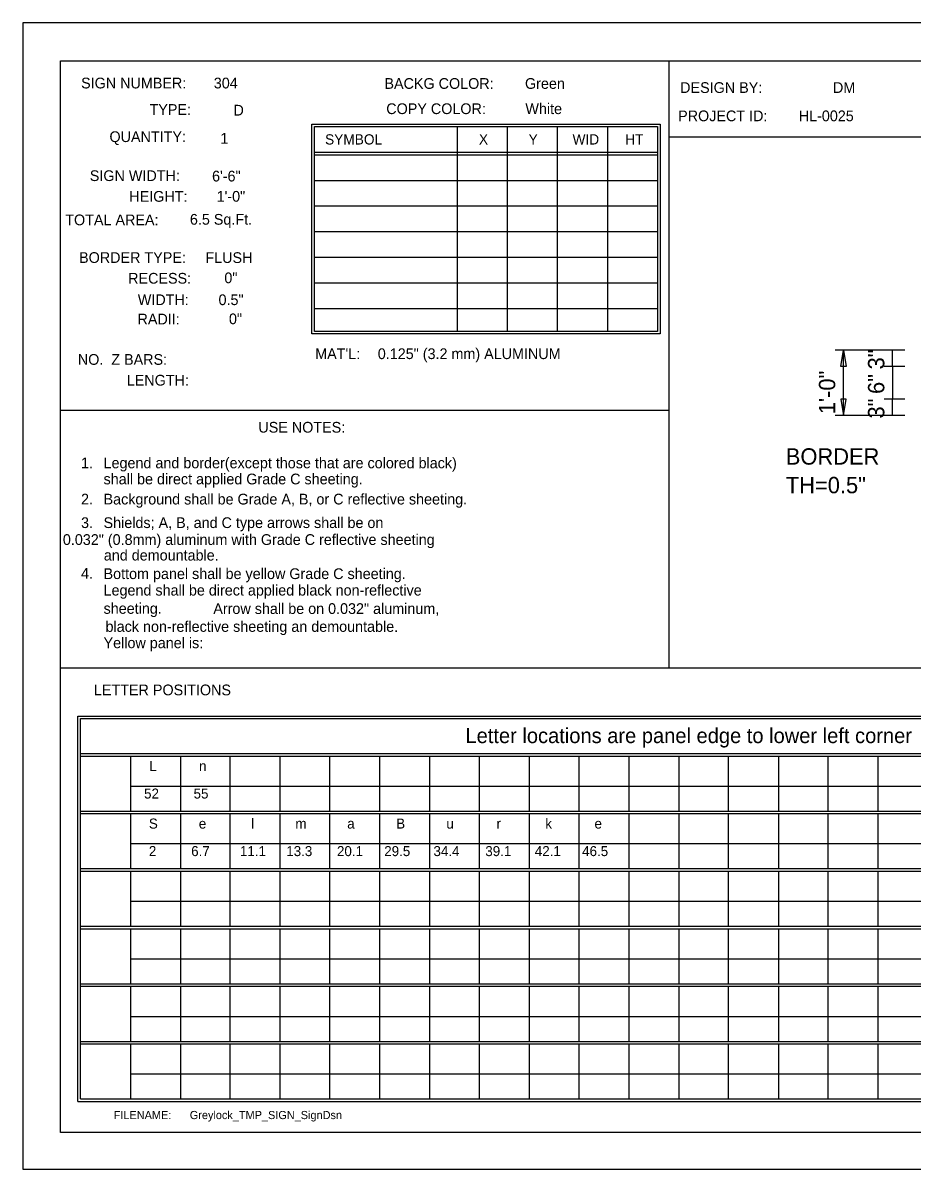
# Model space of a CAD drawing. Extents: x 1708.4 to 1771.6, y 238.3 to 283.4.
# Drawn here: x 1741.57 to 1757.88, y 238.25 to 259.27 of the extents above; entities that cross this region are included whole.
import ezdxf

# ---------------------------------------------------------------- set-up
doc = ezdxf.new("R2010")
doc.units = 0
for name, color, linetype in [('Level 10', 7, 'Continuous'), ('Level 5', 7, 'Continuous'), ('Level 6', 7, 'Continuous'), ('Level 7', 7, 'Continuous'), ('Level 8', 7, 'Continuous'), ('Level 9', 7, 'Continuous')]:
    doc.layers.add(name, color=color, linetype=linetype)

msp = doc.modelspace()

# ---------------------------------------------------------------- linework, layer by layer
at = {"layer": 'Level 5'}
for p, q in [((1756.843, 253.272), (1756.468, 253.272)), ((1756.618, 252.072), (1756.618, 253.272)), ((1757.743, 253.272), (1756.843, 253.272)), ((1757.743, 253.272), (1757.368, 253.272)), ((1757.518, 252.972), (1757.518, 253.272)), ((1757.743, 252.972), (1757.368, 252.972)), ((1757.743, 252.972), (1757.368, 252.972)), ((1757.518, 252.972), (1757.518, 252.372)), ((1757.743, 252.372), (1757.368, 252.372)), ((1757.743, 252.372), (1757.368, 252.372)), ((1757.518, 252.072), (1757.518, 252.372)), ((1756.843, 252.072), (1756.468, 252.072)), ((1757.743, 252.072), (1756.843, 252.072)), ((1757.743, 252.072), (1757.368, 252.072))]:
    msp.add_line(p, q, dxfattribs=at)
for points in [[(1756.618, 253.272), (1756.668, 252.972), (1756.568, 252.972)], [(1756.618, 252.072), (1756.668, 252.371), (1756.568, 252.371)]]:
    msp.add_lwpolyline(points, close=True, dxfattribs=at)
at = {"layer": 'Level 6'}
for p, q in [((1753.415, 258.58), (1753.415, 247.445)), ((1749.531, 257.372), (1749.531, 253.615)), ((1750.45, 257.372), (1750.45, 253.615)), ((1751.37, 257.372), (1751.37, 253.615)), ((1752.29, 257.372), (1752.29, 253.615)), ((1753.415, 257.183), (1770.57, 257.183)), ((1746.917, 256.902), (1753.21, 256.902)), ((1746.917, 256.856), (1753.21, 256.856)), ((1746.917, 256.386), (1753.21, 256.386)), ((1746.917, 255.917), (1753.21, 255.917)), ((1746.917, 255.447), (1753.21, 255.447)), ((1746.917, 254.977), (1753.21, 254.977)), ((1746.917, 254.508), (1753.21, 254.508)), ((1746.917, 254.038), (1753.21, 254.038)), ((1753.415, 252.166), (1742.258, 252.166)), ((1742.258, 247.445), (1753.415, 247.445)), ((1753.415, 247.445), (1770.57, 247.445)), ((1742.622, 245.873), (1764.388, 245.873)), ((1742.622, 245.827), (1764.388, 245.827)), ((1743.539, 245.827), (1743.539, 244.817)), ((1744.457, 245.827), (1744.457, 244.817)), ((1745.366, 245.827), (1745.366, 244.817)), ((1746.283, 245.827), (1746.283, 244.817)), ((1747.192, 245.827), (1747.192, 244.817)), ((1748.11, 245.827), (1748.11, 244.817)), ((1749.027, 245.827), (1749.027, 244.817)), ((1749.936, 245.827), (1749.936, 244.817)), ((1750.854, 245.827), (1750.854, 244.817)), ((1751.762, 245.827), (1751.762, 244.817)), ((1752.68, 245.827), (1752.68, 244.817)), ((1753.598, 245.827), (1753.598, 244.817)), ((1754.506, 245.827), (1754.506, 244.817)), ((1755.424, 245.827), (1755.424, 244.817)), ((1756.332, 245.827), (1756.332, 244.817)), ((1757.25, 245.827), (1757.25, 244.817)), ((1743.539, 245.276), (1764.388, 245.276)), ((1742.622, 244.817), (1764.388, 244.817)), ((1742.622, 244.771), (1764.388, 244.771)), ((1743.539, 244.771), (1743.539, 243.761)), ((1744.457, 244.771), (1744.457, 243.761)), ((1745.366, 244.771), (1745.366, 243.761)), ((1746.283, 244.771), (1746.283, 243.761)), ((1747.192, 244.771), (1747.192, 243.761)), ((1748.11, 244.771), (1748.11, 243.761)), ((1749.027, 244.771), (1749.027, 243.761)), ((1749.936, 244.771), (1749.936, 243.761)), ((1750.854, 244.771), (1750.854, 243.761)), ((1751.762, 244.771), (1751.762, 243.761)), ((1752.68, 244.771), (1752.68, 243.761)), ((1753.598, 244.771), (1753.598, 243.761)), ((1754.506, 244.771), (1754.506, 243.761)), ((1755.424, 244.771), (1755.424, 243.761)), ((1756.332, 244.771), (1756.332, 243.761)), ((1757.25, 244.771), (1757.25, 243.761)), ((1743.539, 244.22), (1764.388, 244.22)), ((1742.622, 243.761), (1764.388, 243.761)), ((1742.622, 243.715), (1764.388, 243.715)), ((1743.539, 243.715), (1743.539, 242.705)), ((1744.457, 243.715), (1744.457, 242.705)), ((1745.366, 243.715), (1745.366, 242.705)), ((1746.283, 243.715), (1746.283, 242.705)), ((1747.192, 243.715), (1747.192, 242.705)), ((1748.11, 243.715), (1748.11, 242.705)), ((1749.027, 243.715), (1749.027, 242.705)), ((1749.936, 243.715), (1749.936, 242.705)), ((1750.854, 243.715), (1750.854, 242.705)), ((1751.762, 243.715), (1751.762, 242.705)), ((1752.68, 243.715), (1752.68, 242.705)), ((1753.598, 243.715), (1753.598, 242.705)), ((1754.506, 243.715), (1754.506, 242.705)), ((1755.424, 243.715), (1755.424, 242.705)), ((1756.332, 243.715), (1756.332, 242.705)), ((1757.25, 243.715), (1757.25, 242.705)), ((1743.539, 243.164), (1764.388, 243.164)), ((1742.622, 242.705), (1764.388, 242.705)), ((1742.622, 242.659), (1764.388, 242.659)), ((1743.539, 242.659), (1743.539, 241.649)), ((1744.457, 242.659), (1744.457, 241.649)), ((1745.366, 242.659), (1745.366, 241.649)), ((1746.283, 242.659), (1746.283, 241.649)), ((1747.192, 242.659), (1747.192, 241.649)), ((1748.11, 242.659), (1748.11, 241.649)), ((1749.027, 242.659), (1749.027, 241.649)), ((1749.936, 242.659), (1749.936, 241.649)), ((1750.854, 242.659), (1750.854, 241.649)), ((1751.762, 242.659), (1751.762, 241.649)), ((1752.68, 242.659), (1752.68, 241.649)), ((1753.598, 242.659), (1753.598, 241.649)), ((1754.506, 242.659), (1754.506, 241.649)), ((1755.424, 242.659), (1755.424, 241.649)), ((1756.332, 242.659), (1756.332, 241.649)), ((1757.25, 242.659), (1757.25, 241.649)), ((1743.539, 242.108), (1764.388, 242.108)), ((1742.622, 241.649), (1764.388, 241.649)), ((1742.622, 241.649), (1764.388, 241.649)), ((1742.622, 241.603), (1764.388, 241.603)), ((1742.622, 241.603), (1764.388, 241.603)), ((1743.539, 241.767), (1743.539, 241.649)), ((1743.539, 241.603), (1743.539, 240.659)), ((1743.539, 241.603), (1743.539, 240.593)), ((1744.457, 241.767), (1744.457, 241.649)), ((1744.457, 241.603), (1744.457, 240.659)), ((1744.457, 241.603), (1744.457, 240.593)), ((1745.366, 241.767), (1745.366, 241.649)), ((1745.366, 241.603), (1745.366, 240.659)), ((1745.366, 241.603), (1745.366, 240.593)), ((1746.283, 241.767), (1746.283, 241.649)), ((1746.283, 241.603), (1746.283, 240.659)), ((1746.283, 241.603), (1746.283, 240.593)), ((1747.192, 241.767), (1747.192, 241.649)), ((1747.192, 241.603), (1747.192, 240.659)), ((1747.192, 241.603), (1747.192, 240.593)), ((1748.11, 241.767), (1748.11, 241.649)), ((1748.11, 241.603), (1748.11, 240.659)), ((1748.11, 241.603), (1748.11, 240.593)), ((1749.027, 241.767), (1749.027, 241.649)), ((1749.027, 241.603), (1749.027, 240.659)), ((1749.027, 241.603), (1749.027, 240.593)), ((1749.936, 241.767), (1749.936, 241.649)), ((1749.936, 241.603), (1749.936, 240.659)), ((1749.936, 241.603), (1749.936, 240.593)), ((1750.854, 241.767), (1750.854, 241.649)), ((1750.854, 241.603), (1750.854, 240.659)), ((1750.854, 241.603), (1750.854, 240.593)), ((1751.762, 241.767), (1751.762, 241.649)), ((1751.762, 241.603), (1751.762, 240.659)), ((1751.762, 241.603), (1751.762, 240.593)), ((1752.68, 241.767), (1752.68, 241.649)), ((1752.68, 241.603), (1752.68, 240.659)), ((1752.68, 241.603), (1752.68, 240.593)), ((1753.598, 241.767), (1753.598, 241.649)), ((1753.598, 241.603), (1753.598, 240.659)), ((1753.598, 241.603), (1753.598, 240.593)), ((1754.506, 241.767), (1754.506, 241.649)), ((1754.506, 241.603), (1754.506, 240.659)), ((1754.506, 241.603), (1754.506, 240.593)), ((1755.424, 241.767), (1755.424, 241.649)), ((1755.424, 241.603), (1755.424, 240.659)), ((1755.424, 241.603), (1755.424, 240.593)), ((1756.332, 241.767), (1756.332, 241.649)), ((1756.332, 241.603), (1756.332, 240.659)), ((1756.332, 241.603), (1756.332, 240.593)), ((1757.25, 241.767), (1757.25, 241.649)), ((1757.25, 241.603), (1757.25, 240.659)), ((1757.25, 241.603), (1757.25, 240.593)), ((1743.539, 241.052), (1764.388, 241.052)), ((1743.539, 241.052), (1764.388, 241.052)), ((1742.622, 240.593), (1764.388, 240.593)), ((1742.622, 240.593), (1764.388, 240.593)), ((1742.622, 240.547), (1764.388, 240.547)), ((1742.622, 240.547), (1764.388, 240.547)), ((1743.539, 240.711), (1743.539, 240.593)), ((1743.539, 240.547), (1743.539, 239.537)), ((1743.539, 240.547), (1743.539, 239.537)), ((1744.457, 240.711), (1744.457, 240.593)), ((1744.457, 240.547), (1744.457, 239.537)), ((1744.457, 240.547), (1744.457, 239.537)), ((1745.366, 240.711), (1745.366, 240.593)), ((1745.366, 240.547), (1745.366, 239.537)), ((1745.366, 240.547), (1745.366, 239.537)), ((1746.283, 240.711), (1746.283, 240.593)), ((1746.283, 240.547), (1746.283, 239.537)), ((1746.283, 240.547), (1746.283, 239.537)), ((1747.192, 240.711), (1747.192, 240.593)), ((1747.192, 240.547), (1747.192, 239.537)), ((1747.192, 240.547), (1747.192, 239.537)), ((1748.11, 240.711), (1748.11, 240.593)), ((1748.11, 240.547), (1748.11, 239.537)), ((1748.11, 240.547), (1748.11, 239.537)), ((1749.027, 240.711), (1749.027, 240.593)), ((1749.027, 240.547), (1749.027, 239.537)), ((1749.027, 240.547), (1749.027, 239.537)), ((1749.936, 240.711), (1749.936, 240.593)), ((1749.936, 240.547), (1749.936, 239.537)), ((1749.936, 240.547), (1749.936, 239.537)), ((1750.854, 240.711), (1750.854, 240.593)), ((1750.854, 240.547), (1750.854, 239.537)), ((1750.854, 240.547), (1750.854, 239.537)), ((1751.762, 240.711), (1751.762, 240.593)), ((1751.762, 240.547), (1751.762, 239.537)), ((1751.762, 240.547), (1751.762, 239.537)), ((1752.68, 240.711), (1752.68, 240.593)), ((1752.68, 240.547), (1752.68, 239.537)), ((1752.68, 240.547), (1752.68, 239.537)), ((1753.598, 240.711), (1753.598, 240.593)), ((1753.598, 240.547), (1753.598, 239.537)), ((1753.598, 240.547), (1753.598, 239.537)), ((1754.506, 240.711), (1754.506, 240.593)), ((1754.506, 240.547), (1754.506, 239.537)), ((1754.506, 240.547), (1754.506, 239.537)), ((1755.424, 240.711), (1755.424, 240.593)), ((1755.424, 240.547), (1755.424, 239.537)), ((1755.424, 240.547), (1755.424, 239.537)), ((1756.332, 240.711), (1756.332, 240.593)), ((1756.332, 240.547), (1756.332, 239.537)), ((1756.332, 240.547), (1756.332, 239.537)), ((1757.25, 240.711), (1757.25, 240.593)), ((1757.25, 240.547), (1757.25, 239.537)), ((1757.25, 240.547), (1757.25, 239.537)), ((1743.539, 239.996), (1764.388, 239.996)), ((1743.539, 239.996), (1764.388, 239.996)), ((1742.575, 239.492), (1764.388, 239.492)), ((1742.622, 239.537), (1764.388, 239.537)), ((1742.622, 239.537), (1764.388, 239.537)), ((1742.622, 239.492), (1764.388, 239.492))]:
    msp.add_line(p, q, dxfattribs=at)
for points in [[(1742.258, 258.58), (1770.57, 258.58), (1770.57, 238.923), (1742.258, 238.923)], [(1746.868, 257.419), (1753.258, 257.419), (1753.258, 253.569), (1746.868, 253.569)], [(1746.917, 257.372), (1753.21, 257.372), (1753.21, 253.615), (1746.917, 253.615)]]:
    msp.add_lwpolyline(points, close=True, dxfattribs=at)
for points in [[(1742.575, 240.659), (1742.575, 246.561), (1764.388, 246.561)], [(1742.622, 240.659), (1742.622, 246.515), (1764.388, 246.515)], [(1742.575, 239.492), (1742.575, 241.767)], [(1742.622, 239.537), (1742.622, 241.767)]]:
    msp.add_lwpolyline(points, dxfattribs=at)
at = {"layer": 'Level 9'}
msp.add_lwpolyline([(1741.568, 238.25), (1771.63, 238.25), (1771.63, 259.274), (1741.568, 259.274)], close=True, dxfattribs=at)

# ---------------------------------------------------------------- texts
at = {"layer": 'Level 10'}
for s, p in [('and demountable.', (1743.052, 249.413)), ('Arrow shall be on 0.032" aluminum,', (1745.06, 248.433)), ('black non-reflective sheeting an demountable.', (1743.083, 248.105))]:
    msp.add_text(s, height=0.19675, dxfattribs=at).set_placement(p)
at = {"layer": 'Level 5'}
for s, p in [('3"', (1757.368, 252.918)), ('1\'-0"', (1756.468, 252.096)), ('6"', (1757.368, 252.468)), ('3"', (1757.368, 252.018))]:
    msp.add_text(s, height=0.3, rotation=90, dxfattribs=at).set_placement(p)
for s, p in [('BORDER', (1755.561, 251.172)), ('TH=0.5"', (1755.561, 250.647))]:
    msp.add_text(s, height=0.3, dxfattribs=at).set_placement(p)
at = {"layer": 'Level 6'}
for s, height, p in [('SIGN NUMBER:', 0.19675, (1742.635, 258.073)), ('BACKG COLOR:', 0.19675, (1748.199, 258.065)), ('DESIGN BY:', 0.1968, (1753.623, 257.99)), ('TYPE:', 0.1968, (1743.89, 257.588)), ('COPY COLOR:', 0.19675, (1748.232, 257.602)), ('PROJECT ID:', 0.19675, (1753.586, 257.471)), ('QUANTITY:', 0.1968, (1743.155, 257.089)), ('SIGN WIDTH:', 0.19675, (1742.795, 256.374)), ('HEIGHT:', 0.1968, (1743.519, 255.994)), ('TOTAL AREA:', 0.19675, (1742.344, 255.563)), ('BORDER TYPE:', 0.19675, (1742.598, 254.872)), ('RECESS:', 0.1968, (1743.498, 254.492)), ('WIDTH:', 0.1968, (1743.675, 254.098)), ('RADII:', 0.1968, (1743.67, 253.744)), ('NO.  Z BARS:', 0.19675, (1742.575, 253.003)), ("MAT'L:", 0.1968, (1746.929, 253.108)), ('LENGTH:', 0.1968, (1743.472, 252.622)), ('USE NOTES: ', 0.19675, (1745.886, 251.759)), ('1.', 0.1968, (1742.634, 251.105)), ('Legend and border(except those that are colored black)', 0.19675, (1743.047, 251.105)), ('2.', 0.1968, (1742.634, 250.441)), ('3.', 0.1968, (1742.634, 250.009)), ('4.', 0.1968, (1742.634, 249.08)), ('LETTER POSITIONS', 0.19675, (1742.87, 246.941)), ('Letter locations are panel edge to lower left corner', 0.27545, (1749.685, 246.064))]:
    msp.add_text(s, height=height, rotation=360, dxfattribs=at).set_placement(p)
for s, height, p in [('DM', 0.1968, (1756.426, 257.99)), ('HL-0025', 0.1968, (1755.798, 257.471)), ('SYMBOL', 0.1878, (1747.11, 257.044)), ('X', 0.188, (1749.932, 257.044)), ('Y', 0.188, (1750.843, 257.044)), ('WID', 0.1878, (1751.649, 257.044)), ('HT', 0.1878, (1752.614, 257.044)), ('0.125" (3.2 mm) ALUMINUM', 0.19675, (1748.077, 253.108)), ('shall be direct applied Grade C sheeting.', 0.19675, (1743.047, 250.81)), ('Background shall be Grade A, B, or C reflective sheeting.', 0.19675, (1743.047, 250.441)), ('Shields; A, B, and C type arrows shall be on', 0.19675, (1743.047, 250.009)), ('       0.032" (0.8mm) aluminum with Grade C reflective sheeting', 0.19675, (1741.789, 249.699)), ('L', 0.184, (1743.887, 245.552)), ('n', 0.184, (1744.798, 245.552)), ('52', 0.1836, (1743.79, 245.047)), ('55', 0.1836, (1744.698, 245.047)), ('S', 0.184, (1743.878, 244.496)), ('e', 0.184, (1744.794, 244.496)), ('l', 0.184, (1745.753, 244.496)), ('m', 0.184, (1746.565, 244.496)), ('a', 0.184, (1747.516, 244.496)), ('B', 0.184, (1748.414, 244.496)), ('u', 0.184, (1749.334, 244.496)), ('r', 0.184, (1750.255, 244.496)), ('k', 0.184, (1751.149, 244.496)), ('e', 0.184, (1752.052, 244.496)), ('2', 0.184, (1743.878, 243.991)), ('6.7', 0.1836, (1744.654, 243.991)), ('11.1', 0.1836, (1745.548, 243.991)), ('13.3', 0.1836, (1746.398, 243.991)), ('20.1', 0.1836, (1747.328, 243.991)), ('29.5', 0.1836, (1748.195, 243.991)), ('34.4', 0.1836, (1749.098, 243.991)), ('39.1', 0.1836, (1750.049, 243.991)), ('42.1', 0.1836, (1750.957, 243.991)), ('46.5', 0.1836, (1751.825, 243.991))]:
    msp.add_text(s, height=height, dxfattribs=at).set_placement(p)
at = {"layer": 'Level 7'}
for s, height, p in [('304', 0.1968, (1745.069, 258.073)), ('Green', 0.1968, (1750.777, 258.065)), ('D', 0.197, (1745.43, 257.575)), ('1', 0.197, (1745.189, 257.059)), ('6\'-6"', 0.1968, (1745.037, 256.366)), ('1\'-0"', 0.1968, (1745.121, 255.995)), ('6.5 Sq.Ft.', 0.1968, (1744.631, 255.573)), ('FLUSH', 0.1968, (1744.915, 254.871)), ('0"', 0.1968, (1745.263, 254.5)), ('0.5"', 0.1968, (1745.156, 254.098)), ('0"', 0.1968, (1745.347, 253.748))]:
    msp.add_text(s, height=height, rotation=360, dxfattribs=at).set_placement(p)
for s, height, p in [('White', 0.1968, (1750.784, 257.602)), ('Bottom panel shall be yellow Grade C sheeting.', 0.19675, (1743.047, 249.073)), ('Legend shall be direct applied black non-reflective', 0.19675, (1743.047, 248.771)), ('sheeting.', 0.1968, (1743.047, 248.436)), ('Yellow panel is:', 0.19675, (1743.047, 247.805))]:
    msp.add_text(s, height=height, dxfattribs=at).set_placement(p)
at = {"layer": 'Level 8'}
for s, height, p in [('FILENAME:', 0.1497, (1743.233, 239.167)), ('Greylock_TMP_SIGN_SignDsn', 0.14966, (1744.629, 239.167))]:
    msp.add_text(s, height=height, rotation=360, dxfattribs=at).set_placement(p)

doc.saveas('drawing.dxf')
